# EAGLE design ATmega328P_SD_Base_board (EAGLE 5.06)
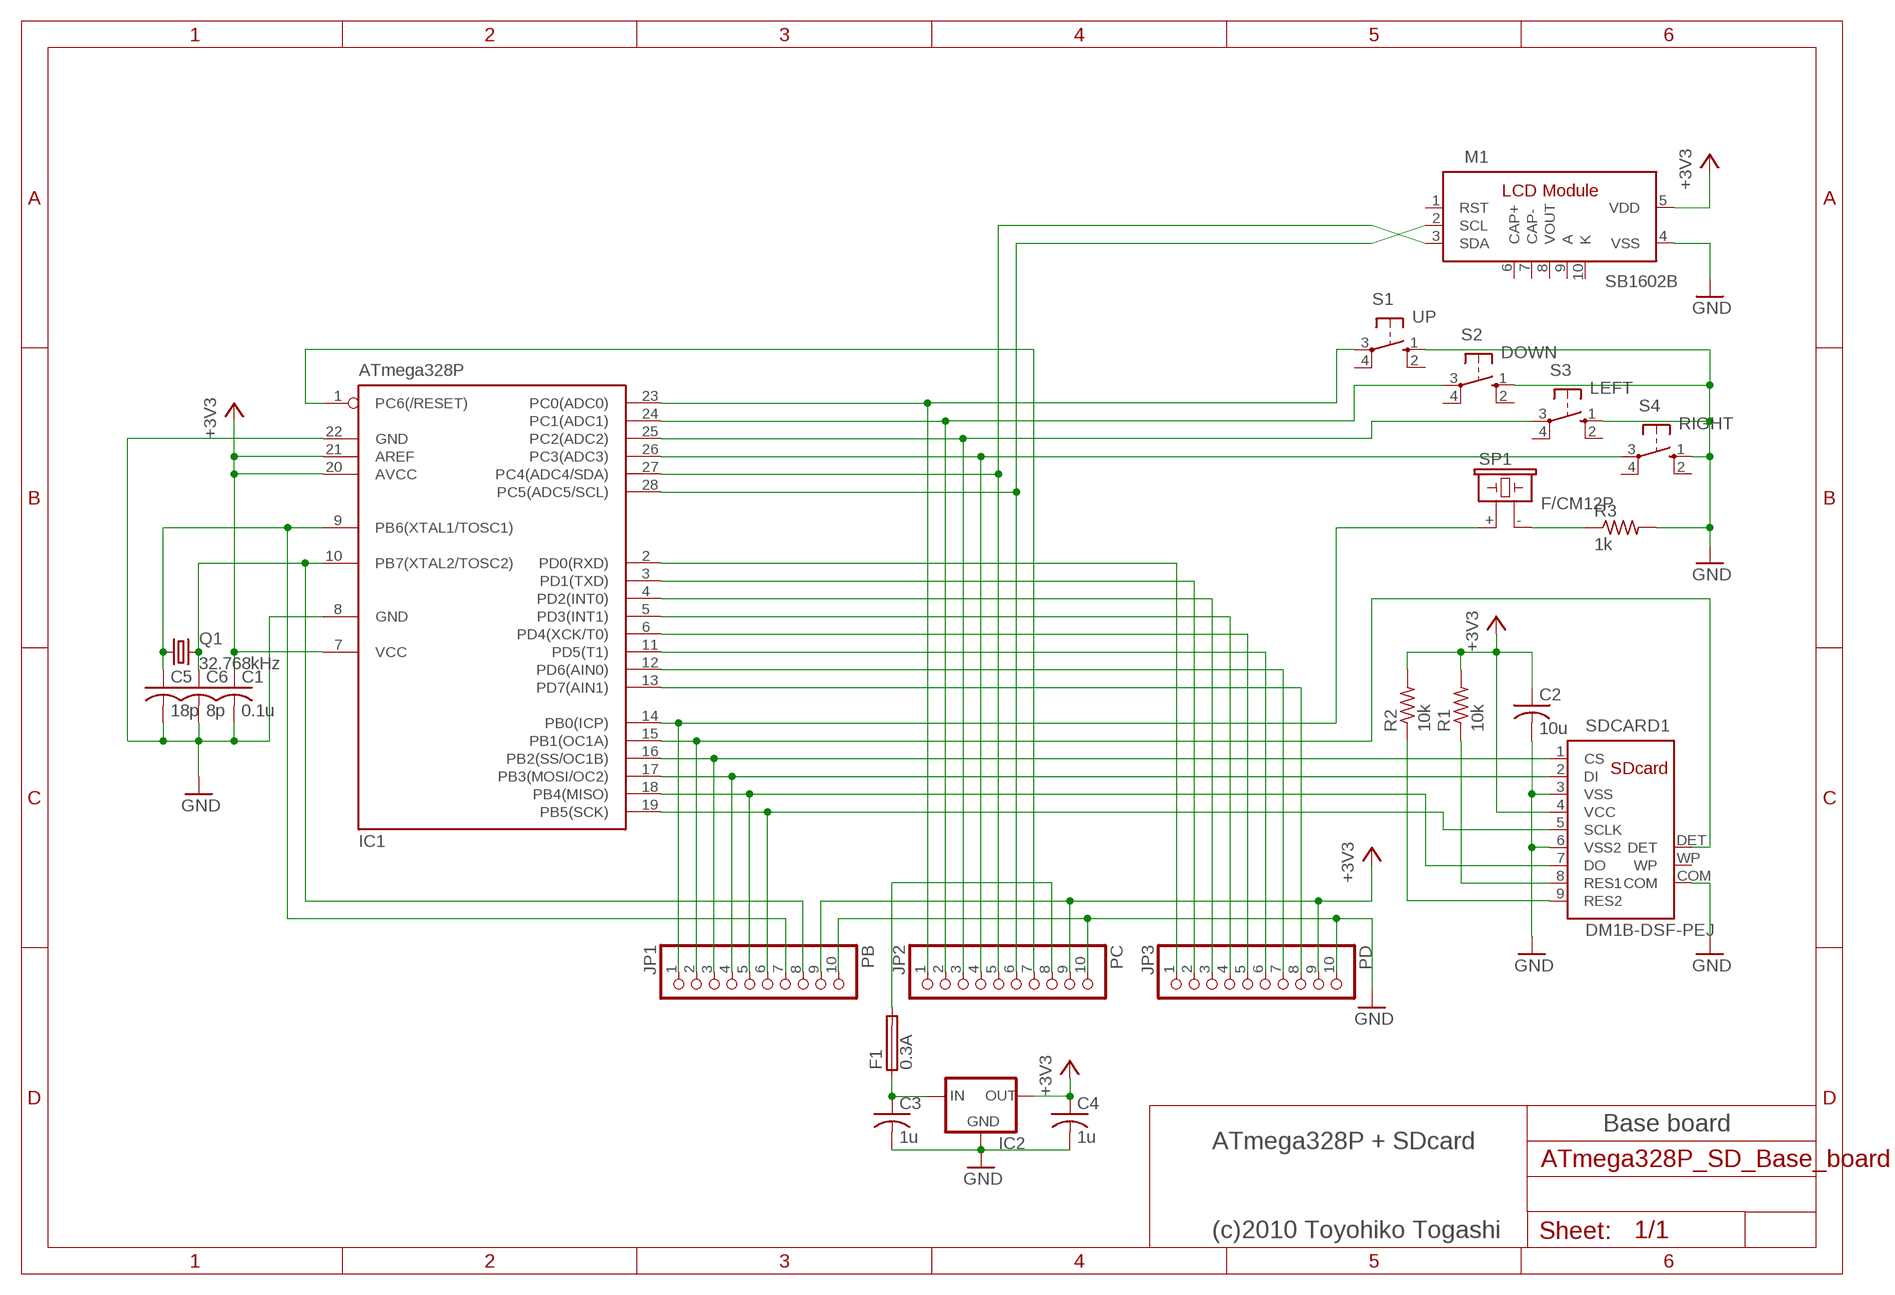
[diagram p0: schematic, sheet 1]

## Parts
C1  0.1u  C-US025-024X044  [C025-024X044]
C2  10u  C-US025-024X044  [C025-024X044]
C3  1u  C-US025-024X044  [C025-024X044]
C4  1u  C-US025-024X044  [C025-024X044]
C5  18p  C-US025-024X044  [C025-024X044]
C6  8p  C-US025-024X044  [C025-024X044]
F1  0.3A  TE5  [TE5]
IC1  ATmega328P  MEGA8-P  [DIL28-3]
IC2  XC63FPL  [TO92]
JP1  PB  PINHD-1X10  [1X10]
JP2  PC  PINHD-1X10  [1X10]
JP3  PD  PINHD-1X10  [1X10]
M1  SB1602B  [SB1602B]
Q1  32.768kHz  CRYSTALTC26H  [TC26H]
R1  10k  R-US_0204/5  [0204/5]
R2  10k  R-US_0204/5  [0204/5]
R3  1k  R-US_0204/5  [0204/5]
S1  UP  10-XX  [B3F-10XX]
S2  DOWN  10-XX  [B3F-10XX]
S3  LEFT  10-XX  [B3F-10XX]
S4  RIGHT  10-XX  [B3F-10XX]
SDCARD1  DM1B-DSF-PEJ  [DM1B]
SP1  F/CM12P  [F/CM12P]

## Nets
+3V3: C1.1 C2.1 C4.1 IC1.7(VCC) IC1.20(AVCC) IC1.21(AREF) IC2.3(OUT) JP1.9 JP2.9 JP3.9 M1.5(VDD) R1.2 R2.2 SDCARD1.4(VCC)
GND: C1.2 C2.2 C3.2 C4.2 C5.2 C6.2 IC1.8(GND) IC1.22(GND) IC2.2(GND) JP1.10 JP2.10 JP3.10 M1.4(VSS) R3.2 S1.1(S) S2.1(S) S3.1(S) S4.1(S) SDCARD1.3(VSS) SDCARD1.6(VSS2) SDCARD1.COM
N$1: IC1.16(PB2(SS/OC1B)) JP1.3 SDCARD1.1(CS)
N$2: IC1.17(PB3(MOSI/OC2)) JP1.4 SDCARD1.2(DI)
N$3: IC1.18(PB4(MISO)) JP1.5 SDCARD1.7(DO)
N$4: IC1.19(PB5(SCK)) JP1.6 SDCARD1.5(SCLK)
N$5: IC1.27(PC4(ADC4/SDA)) JP2.5 M1.3(SDA)
N$6: IC1.28(PC5(ADC5/SCL)) JP2.6 M1.2(SCL)
N$7: IC1.2(PD0(RXD)) JP3.1
N$8: IC1.3(PD1(TXD)) JP3.2
N$9: R1.1 SDCARD1.8(RES1)
N$10: R2.1 SDCARD1.9(RES2)
N$11: IC1.4(PD2(INT0)) JP3.3
N$12: IC1.5(PD3(INT1)) JP3.4
N$13: IC1.6(PD4(XCK/T0)) JP3.5
N$14: IC1.11(PD5(T1)) JP3.6
N$15: IC1.12(PD6(AIN0)) JP3.7
N$16: IC1.13(PD7(AIN1)) JP3.8
N$17: R3.1 SP1.-
N$18: IC1.23(PC0(ADC0)) JP2.1 S1.3(P)
N$19: IC1.24(PC1(ADC1)) JP2.2 S2.3(P)
N$20: IC1.25(PC2(ADC2)) JP2.3 S3.3(P)
N$21: IC1.26(PC3(ADC3)) JP2.4 S4.3(P)
N$22: IC1.14(PB0(ICP)) JP1.1 SP1.+
N$23: IC1.15(PB1(OC1A)) JP1.2 SDCARD1.DET
N$24: C5.1 IC1.9(PB6(XTAL1/TOSC1)) JP1.7 Q1.1
N$25: C3.1 F1.1 IC2.1(IN)
N$26: IC1.1(PC6(/RESET)) JP2.7
N$27: F1.2 JP2.8
N$28: C6.1 IC1.10(PB7(XTAL2/TOSC2)) JP1.8 Q1.2
Unconnected: M1.1(RST) M1.6(CAP+) M1.7(CAP-) M1.8(VOUT) S1.2(S1) S1.4(P1) S2.2(S1) S2.4(P1) S3.2(S1) S3.4(P1) S4.2(S1) S4.4(P1) SDCARD1.WP

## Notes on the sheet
- Base board
- ATmega328P + SDcard
- (c)2010 Toyohiko Togashi

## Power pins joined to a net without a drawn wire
A: M1.9(A)
K: M1.10(K)

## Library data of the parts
C1-C6 = rcl:C-US: CAPACITOR, American symbol
F1 = fuse:TE5: FUSE
IC1 = atmel:MEGA8-P: MICROCONTROLLER 8 Kbytes FLASH, 1 kbytes SRAM, 512 bytes EEPROM, USART, 4-channel 10 bit ADC, 2-channel 8 bit ADC Pin compatible with Atmega48, ATMega88, ATMega168 Source: avr.lbr
IC2 = v-reg:XC63FP: Positiv Voltage Regulators www.torex.co.jp/english/product/pro02/pdf/0201_xc62fp.pdf
JP1-JP3 = pinhead:PINHD-1X10: PIN HEADER
M1 = TOG:SB1602B: Strawberry Linux Co.,Ltd. I2C LCD Module Controler: ST7032i
Q1 = crystal:CRYSTAL: CRYSTAL
R1-R3 = rcl:R-US_: RESISTOR, American symbol
S1-S4 = switch-omron:10-XX: OMRON SWITCH
SDCARD1 = TOG:DM1B-DSF-PEJ: SDcard connector reverse type HIROSE
SP1 = buzzer:F/CM12P: BUZZER

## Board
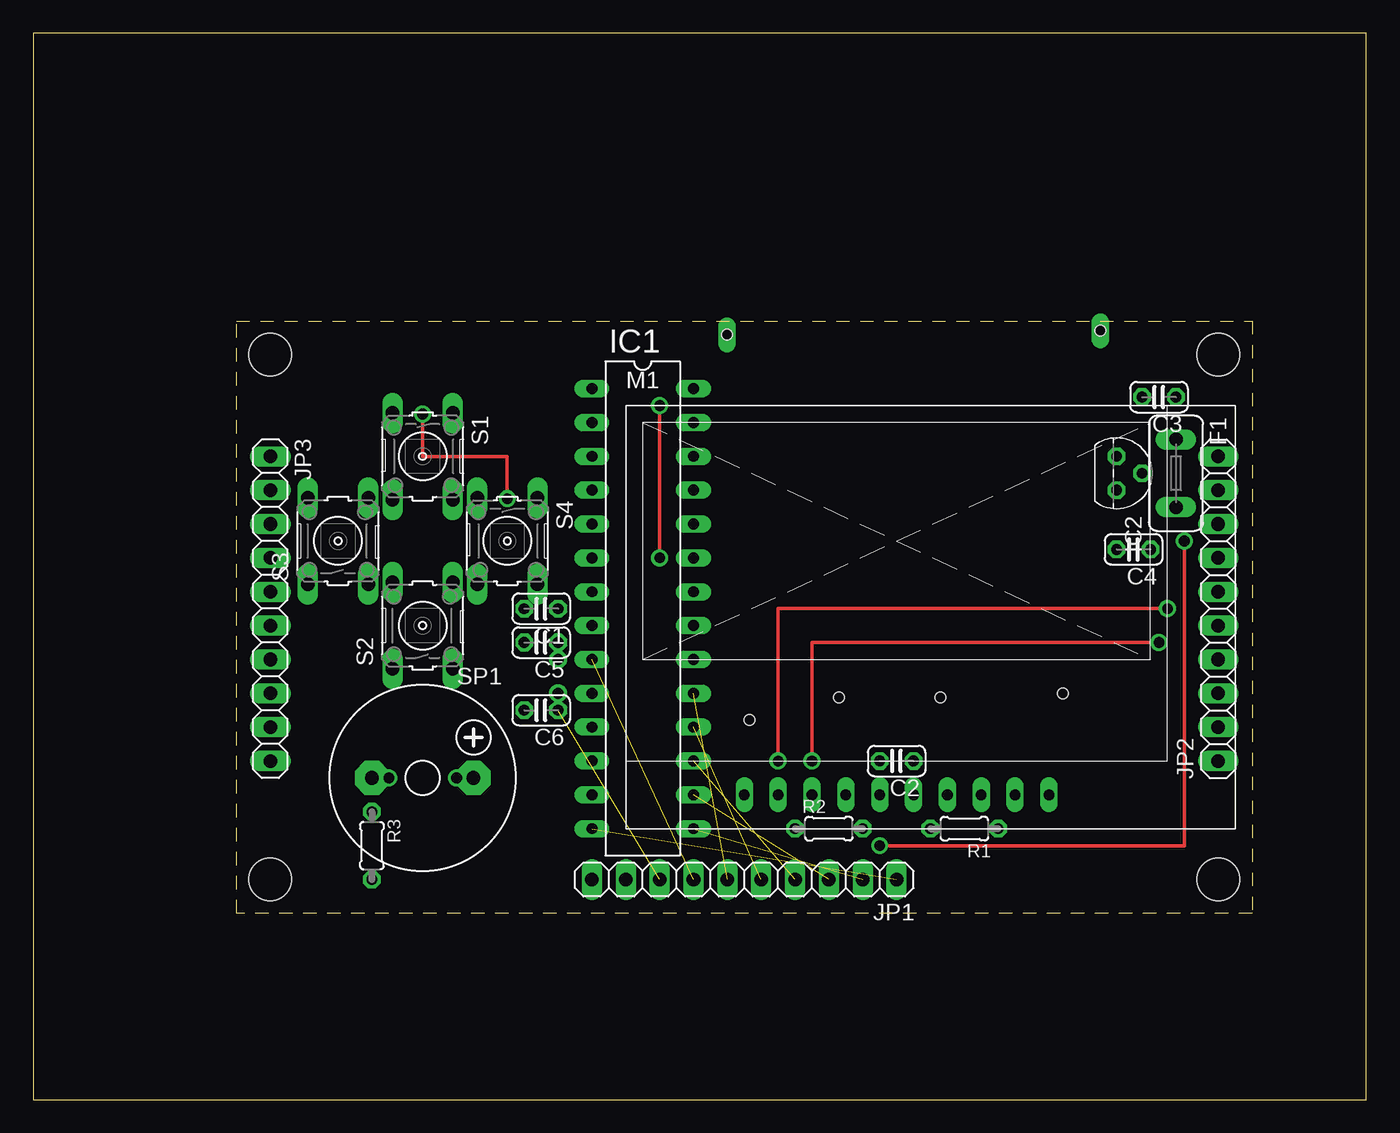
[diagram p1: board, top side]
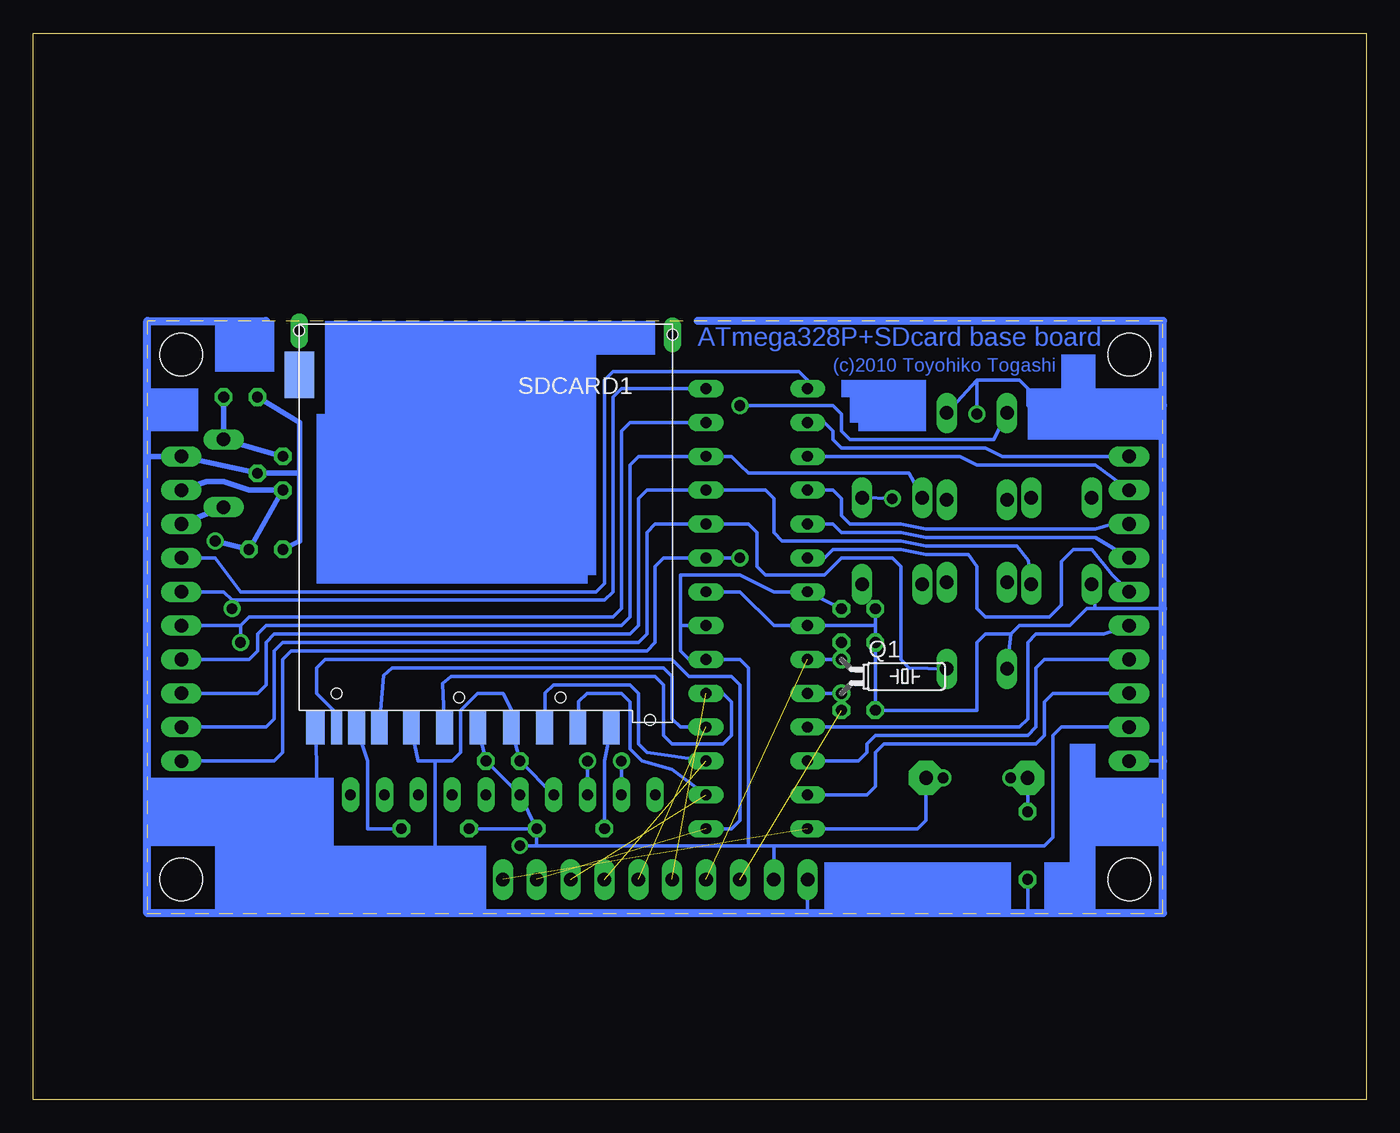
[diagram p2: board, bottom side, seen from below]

Size 100 x 80 mm. Coordinates in mm from the lower left corner, seen from the top.
Outline: 0,0 100,0 100,80 0,80 0,0
Outline: 15.24,58.42 91.44,58.42 91.44,13.97 15.24,13.97 15.24,58.42
Copper layers (1*16): Top 0.035mm / dielectric 1.5mm / Bottom 0.035mm
Design rules "default": minimum track width 10mil, minimum drill 24mil, track to track 8mil, track to pad 8mil, pad to pad 8mil, via to via 8mil, smd to smd 8mil, copper to edge 40mil, drill to drill 8mil, minimum pad ring 10mil, minimum via ring 8mil, stop-mask expansion 4mil, vias tented up to drill 0mil, thermal gap 10mil
Holes 3.2 mm at 17.78,55.88 88.9,55.88 88.9,16.51 17.78,16.51

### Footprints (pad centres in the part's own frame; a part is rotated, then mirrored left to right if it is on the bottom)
C025-024X044 = drill 0.813 octagon: 1 -1.27,0; 2 1.27,0
TE5 = drill 1.016 long: 1 -2.54,0; 2 2.54,0
DIL28-3 = drill 0.813 long: 1 -16.51,-3.81; 2 -13.97,-3.81; 3 -11.43,-3.81; 4 -8.89,-3.81; 5 -6.35,-3.81; 6 -3.81,-3.81; 7 -1.27,-3.81; 8 1.27,-3.81; 9 3.81,-3.81; 10 6.35,-3.81; 11 8.89,-3.81; 12 11.43,-3.81; 13 13.97,-3.81; 14 16.51,-3.81; 15 16.51,3.81; 16 13.97,3.81; 17 11.43,3.81; 18 8.89,3.81; 19 6.35,3.81; 20 3.81,3.81; 21 1.27,3.81; 22 -1.27,3.81; 23 -3.81,3.81; 24 -6.35,3.81; 25 -8.89,3.81; 26 -11.43,3.81; 27 -13.97,3.81; 28 -16.51,3.81
TO92 = drill 0.813 octagon: 1 -1.27,0; 2 0,1.905; 3 1.27,0
1X10 = drill 1.016 long: 1 -11.43,0; 2 -8.89,0; 3 -6.35,0; 4 -3.81,0; 5 -1.27,0; 6 1.27,0; 7 3.81,0; 8 6.35,0; 9 8.89,0; 10 11.43,0
SB1602B = drill 0.8 long: 1 -13.97,-12.7; 2 -11.43,-12.7; 3 -8.89,-12.7; 4 -6.35,-12.7; 5 -3.81,-12.7; 6 -1.27,-12.7; 7 1.27,-12.7; 8 3.81,-12.7; 9 6.35,-12.7; 10 8.89,-12.7
TC26H = drill 0.813 round: 1 -1.27,0; 2 1.27,0
0204/5 = drill 0.813 octagon: 1 -2.54,0; 2 2.54,0
B3F-10XX = drill 1.016 long: 1 -3.251,2.261; 2 3.251,2.261; 3 -3.251,-2.261; 4 3.251,-2.261
DM1B = smd 1.25 x 2.5: 1 -6.9,15.3; 2 -4.4,15.3; 3 -1.9,15.3; 4 0.6,15.3; 5 3.1,15.3; 6 5.6,15.3; 7 8,15.3; 8 9.7,15.3; 9 -9.4,15.3 | smd 1.4 x 2.5: COM 12.8,15.3 | smd 0.8 x 2.5: DET 11.2,15.3 | drill 0.8 pad 1.2 long: P$17 14,-14.5 | drill 0.8 pad 1.27 long: P$18 -14,-14.2 | smd 2.2 x 3.5: WP 14,-11.2 | hole 0.8: -12.3,14.7; -5.6,13; 2,13; 11.2,12.7; -14,-14.2; 14,-14.5
F/CM12P = drill 1.016 pad 2.54 octagon: + 3.81,0; - -3.81,0

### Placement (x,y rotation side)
C1  38.1,36.83 180 top
C2  64.77,25.4 180 top
C3  84.45,52.7 180 top
C4  82.55,41.27 180 top
C5  38.1,34.29 180 top
C6  38.1,29.21 180 top
F1  85.72,46.99 270 top
IC1  45.72,36.83 270 top
IC2  81.28,46.99 270 top
JP1  53.34,16.51 180 top
JP2  88.9,36.83 90 top
JP3  17.78,36.83 270 top
M1  67.31,35.56 0 top
Q1  39.37,31.75 270 bottom
R1  69.85,20.32 180 top
R2  59.69,20.32 0 top
R3  25.4,19.05 270 top
S1  29.21,48.26 270 top
S2  29.21,35.56 90 top
S3  22.86,41.91 90 top
S4  35.56,41.91 270 top
SDCARD1  66.04,43.18 180 bottom
SP1  29.21,24.13 0 top

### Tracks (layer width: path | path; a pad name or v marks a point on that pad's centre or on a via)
+3V3  (via drill 0.8 pad 1.27)
  Top 0.254: v63.5,19.05 86.36,19.05 v86.36,41.91
  Bottom 0.254: SDCARD1.4 C2.1 M1.5 R2.2 | R2.2 R1.2 | C1.1 IC1.7 44.45,38.1 46.99,39.37 51.44,39.37 51.44,35.56 | 44.45,19.05 46.35,19.05 | 44.45,19.05 24.13,19.05 23.5,19.68 23.5,27.3 22.86,27.94 JP3.9 | 44.45,19.05 JP1.9 | 51.44,35.56 51.44,33.66 50.8,33.02 IC1.20 46.99,33.02 46.35,32.38 46.35,19.05 | 51.44,35.56 IC1.21 | 46.35,19.05 62.23,19.05 | 62.23,19.05 v63.5,19.05 | 62.23,19.05 R2.2
  Bottom 0.406: JP2.9 87,46.35 85.72,46.35 83.82,45.72 IC2.3 C4.1 v86.36,41.91
GND  (via drill 0.8 pad 1.27)
  Top 0.254: v29.21,51.44 29.21,48.26 35.56,48.26 v35.56,45.09
  Bottom 0.254: M1.4 C2.2 SDCARD1.3 64.14,29.22 64.77,30.48 66.67,30.48 67.94,29.21 67.94,26.04 68.58,25.4 69.85,25.4 | SDCARD1.COM 78.74,25.4 78.74,13.97 | IC1.22 46.99,38.1 44.45,35.56 IC1.8 36.83,35.56 | 69.85,13.97 69.85,25.4 | 69.85,25.4 71.12,25.4 SDCARD1.6 | 15.24,25.4 JP3.10 | 36.83,35.56 C5.2 C6.2 29.21,29.21 29.21,34.29 28.57,34.92 26.67,34.92 | 36.83,35.56 C1.2 | 29.21,53.98 26.04,53.98 25.4,53.34 25.4,52.07 15.24,52.07 | 26.67,34.92 26.04,35.56 22.23,35.56 20.95,36.83 20.32,36.83 | 15.24,36.83 20.32,36.83 | 41.91,13.97 JP1.10 | 26.67,34.92 S2.1 | 29.21,53.98 S1.1 | v35.56,45.09 S4.1 | 29.21,53.98 v29.21,51.44 | 25.4,13.97 R3.2 | 20.32,36.83 S3.1
  Bottom 0.406: C4.2 80.01,41.91 80.01,46.99 | 80.01,46.99 80.01,50.8 C3.2 | 91.44,48.26 JP2.10 IC2.2 80.01,46.99
  Bottom 0.61: 50.16,58.42 15.24,58.42 15.24,52.07 15.24,36.83 15.24,25.4 15.24,13.97 25.4,13.97 41.91,13.97 69.85,13.97 78.74,13.97 91.44,13.97 91.44,48.26 91.44,58.42 82.55,58.42
N$1  (1 unrouted)
  Bottom 0.254: IC1.16 52.07,24.77 54.35,25.4 55.24,26.3 55.24,29.84 55.88,30.48 58.44,30.48 59.08,29.86 SDCARD1.1
N$2  (1 unrouted)
  Bottom 0.254: IC1.17 53.98,26.04 54.61,26.67 54.61,30.48 55.24,31.11 60.97,31.11 61.6,30.49 SDCARD1.2
N$3  (1 unrouted)
  Bottom 0.254: IC1.18 51.44,27.94 52.07,28.57 52.07,31.75 52.7,32.38 73.08,32.38 73.71,31.8 SDCARD1.7
N$4  (1 unrouted)
  Bottom 0.254: IC1.19 48.26,30.48 47.62,29.84 47.62,27.3 48.26,26.67 52.07,26.67 52.7,27.3 52.7,31.11 53.34,31.75 68.67,31.75 69.29,31.21 SDCARD1.5
N$5  (via drill 0.8 pad 1.27)
  Top 0.254: v58.42,25.4 58.42,34.29 v84.45,34.29
  Bottom 0.254: 84.45,35.56 JP2.5 | 84.45,35.56 83.82,36.2 56.52,36.2 55.88,36.83 55.88,50.16 55.24,50.8 IC1.27 | M1.3 v58.42,25.4 | 84.45,35.56 v84.45,34.29
N$6  (via drill 0.8 pad 1.27)
  Top 0.254: v55.88,25.4 55.88,34.29 55.88,36.83 v85.09,36.83
  Bottom 0.254: JP2.6 85.72,38.1 85.09,37.47 | 85.09,37.47 57.15,37.47 56.52,38.1 56.52,52.7 55.88,53.34 IC1.28 | M1.2 v55.88,25.4 | 85.09,37.47 v85.09,36.83
N$7
  Bottom 0.254: IC1.2 40.64,50.8 40.01,50.16 40.01,49.53 39.37,48.9 28.57,48.9 27.3,48.26 JP3.1
N$8
  Bottom 0.254: JP3.2 20.32,47.62 29.21,47.62 30.48,48.26 IC1.3
N$9
  Bottom 0.254: R1.1 74.93,20.32 74.93,25.4 SDCARD1.8
N$10
  Bottom 0.254: R2.1 57.15,25.4 SDCARD1.9
N$11
  Bottom 0.254: IC1.4 40.01,45.72 39.37,45.09 39.37,43.81 38.73,43.18 34.92,43.18 33.02,42.8 20.32,42.8 19.05,43.18 JP3.3
N$12
  Bottom 0.254: IC1.5 40.01,43.18 39.37,42.55 34.92,42.55 33.02,42.16 20.32,42.16 JP3.4
N$13
  Bottom 0.254: IC1.6 40.64,40.64 40.01,41.27 34.92,41.27 33.02,40.89 29.84,40.89 29.21,40.01 29.21,36.83 28.57,36.2 23.76,36.2 22.86,37.09 22.86,40.38 21.96,41.27 20.57,41.27 19.05,39.37 JP3.5
N$14
  Bottom 0.254: IC1.11 26.04,27.94 25.4,28.57 25.4,34.29 24.77,34.92 19.68,34.92 JP3.6
N$15
  Bottom 0.254: IC1.12 38.1,25.4 37.47,26.04 37.47,26.67 36.83,27.3 25.4,27.3 24.77,27.94 24.77,32.38 24.13,33.02 JP3.7
N$16
  Bottom 0.254: JP3.8 23.5,30.48 24.13,29.84 24.13,27.3 24.77,26.67 36.2,26.67 36.83,26.04 36.83,23.5 37.47,22.86 IC1.13
N$17
  Bottom 0.254: R3.1 SP1.-
N$18  (via drill 0.8 pad 1.27)
  Top 0.254: v46.99,52.07 v46.99,40.64
  Bottom 0.254: S1.3 27.94,49.53 38.73,49.53 39.37,50.16 39.37,51.44 40.01,52.07 v46.99,52.07 | JP2.1 81.92,25.4 81.28,26.04 81.28,33.02 80.64,33.66 53.98,33.66 53.34,34.29 53.34,40.01 52.7,40.64 IC1.23 v46.99,40.64
N$19
  Bottom 0.254: S2.3 34.3,32.37 34.92,33.01 34.92,40.01 35.56,40.64 39.37,40.64 40.64,39.37 45.09,39.37 45.72,40.01 45.72,42.55 46.35,43.18 IC1.24 53.34,43.18 53.98,42.55 53.98,34.92 54.61,34.29 81.28,34.29 81.92,33.66 81.92,28.57 82.55,27.94 JP2.2
N$20
  Bottom 0.254: S3.3 25.33,40.45 26.22,41.53 33.02,41.53 34.92,41.91 43.81,41.91 44.45,42.55 44.45,45.09 45.09,45.72 IC1.25 53.98,45.72 54.61,45.09 54.61,35.56 55.24,34.92 81.92,34.92 82.55,34.29 82.55,31.11 83.19,30.48 JP2.3
N$21
  Bottom 0.254: S4.3 34.29,46.99 46.35,46.99 46.99,47.62 47.62,48.26 IC1.26 54.61,48.26 55.24,47.62 55.24,36.2 55.88,35.56 82.55,35.56 83.19,34.92 83.19,33.66 83.82,33.02 JP2.4
N$22  (1 unrouted)
  Bottom 0.254: SP1.+ 33.02,20.95 33.66,20.32 IC1.14
N$23  (1 unrouted)
  Bottom 0.254: IC1.15 47.62,20.32 46.99,20.95 46.99,31.11 47.62,31.75 50.8,31.75 52.07,33.02 78.11,33.02 78.74,32.38 78.74,30.48 77.47,29.21 SDCARD1.DET
N$24  (1 unrouted)
  Bottom 0.254: IC1.9 Q1.1 C5.1
N$25
  Bottom 0.406: IC2.1 F1.1 C3.1
N$26
  Bottom 0.254: JP2.7 86.36,40.64 84.45,38.1 57.78,38.1 57.15,38.73 57.15,53.98 56.52,54.61 42.55,54.61 41.91,53.98 IC1.1
N$27
  Bottom 0.406: JP2.8 F1.2
N$28  (1 unrouted)
  Bottom 0.254: IC1.10 Q1.2 C6.1
N$29  (via drill 0.8 pad 1.27)
  other vias: 26.67,24.13
N$30  (via drill 0.8 pad 1.27)
  other vias: 31.75,24.13
(copper drawn outside any net)
  shapes: Bottom area x18

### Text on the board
Bottom: ATmega328P+SDcard base board | (c)2010 Toyohiko Togashi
